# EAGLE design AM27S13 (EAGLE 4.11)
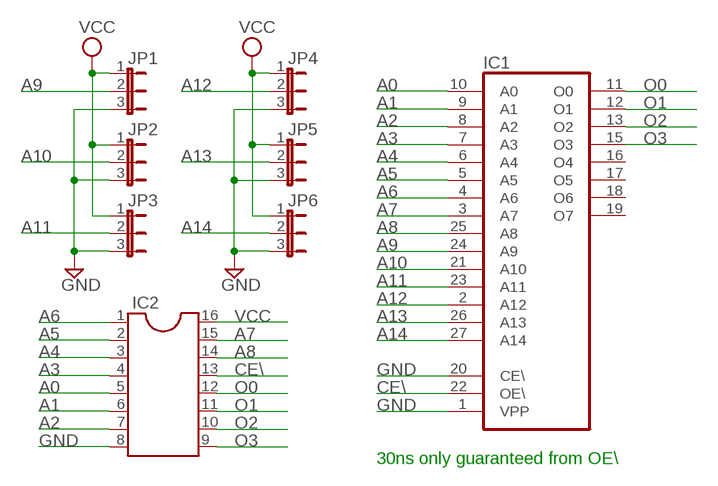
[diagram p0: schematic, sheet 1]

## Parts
IC1  27256  [DIL28]
IC2  DIL16  [DIL16]
JP1  JP2E  [JP2]
JP2  JP2E  [JP2]
JP3  JP2E  [JP2]
JP4  JP2E  [JP2]
JP5  JP2E  [JP2]
JP6  JP2E  [JP2]

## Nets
A0: IC1.10(A0) IC2.5
A1: IC1.9(A1) IC2.6
A2: IC1.8(A2) IC2.7
A3: IC1.7(A3) IC2.4
A4: IC1.6(A4) IC2.3
A5: IC1.5(A5) IC2.2
A6: IC1.4(A6) IC2.1
A7: IC1.3(A7) IC2.15
A8: IC1.25(A8) IC2.14
A9: IC1.24(A9) JP1.2
A10: IC1.21(A10) JP2.2
A11: IC1.23(A11) JP3.2
A12: IC1.2(A12) JP4.2
A13: IC1.26(A13) JP5.2
A14: IC1.27(A14) JP6.2
CE\: IC1.22(OE\) IC2.13
GND: IC1.1(VPP) IC1.20(CE\) IC2.8 JP1.3 JP2.3 JP3.3 JP4.3 JP5.3 JP6.3
O0: IC1.11(O0) IC2.12
O1: IC1.12(O1) IC2.11
O2: IC1.13(O2) IC2.10
O3: IC1.15(O3) IC2.9
VCC: IC2.16 JP1.1 JP2.1 JP3.1 JP4.1 JP5.1 JP6.1
Unconnected: IC1.16(O4) IC1.17(O5) IC1.18(O6) IC1.19(O7)

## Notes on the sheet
- 30ns only guaranteed from OE\

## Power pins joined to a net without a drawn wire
GND: IC1.14(GND)
VCC: IC1.28(VCC)

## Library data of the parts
IC1 = memory:27256: MEMORY
IC2 = ic-package:DIL16: Dual In Line
JP1-JP6 = jumper:JP2E: JUMPER

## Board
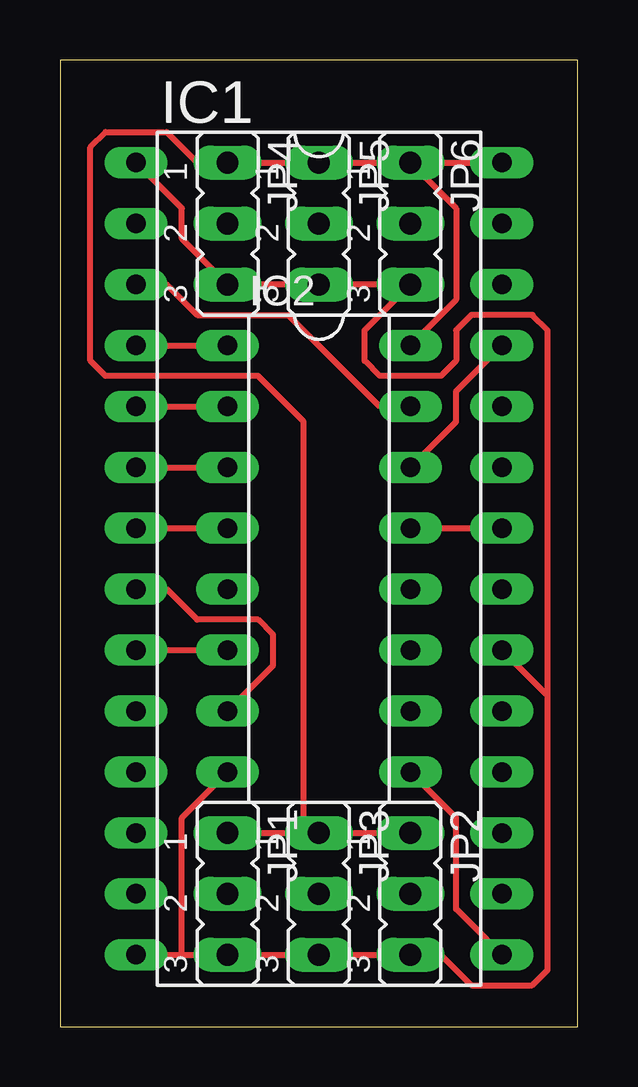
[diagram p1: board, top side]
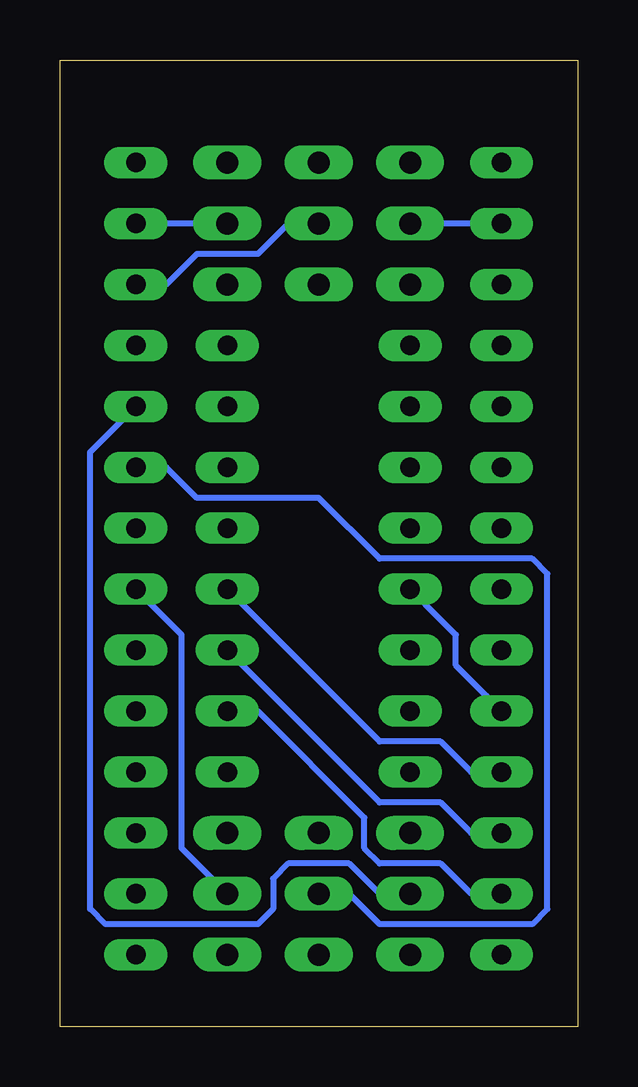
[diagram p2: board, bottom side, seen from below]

Size 21.57 x 40.31 mm. Coordinates in mm from the lower left corner, seen from the top.
Outline: 0,0 21.57,0 21.57,40.31 0,40.31 0,0
Copper layers (1*16): Top 0.035mm / dielectric 1.5mm / Bottom 0.035mm
Design rules "olimex8mil": minimum track width 10mil, minimum drill 24mil, track to track 8mil, track to pad 8mil, pad to pad 8mil, via to via 8mil, smd to smd 8mil, copper to edge 40mil, drill to drill 10mil, minimum pad ring 10mil, minimum via ring 8mil, stop-mask expansion 0mil, vias tented up to drill 0mil, thermal gap 10mil

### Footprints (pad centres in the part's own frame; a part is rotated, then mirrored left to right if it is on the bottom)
DIL28 = drill 0.813 long: 1 -16.51,-7.62; 2 -13.97,-7.62; 3 -11.43,-7.62; 4 -8.89,-7.62; 5 -6.35,-7.62; 6 -3.81,-7.62; 7 -1.27,-7.62; 8 1.27,-7.62; 9 3.81,-7.62; 10 6.35,-7.62; 11 8.89,-7.62; 12 11.43,-7.62; 13 13.97,-7.62; 14 16.51,-7.62; 15 16.51,7.62; 16 13.97,7.62; 17 11.43,7.62; 18 8.89,7.62; 19 6.35,7.62; 20 3.81,7.62; 21 1.27,7.62; 22 -1.27,7.62; 23 -3.81,7.62; 24 -6.35,7.62; 25 -8.89,7.62; 26 -11.43,7.62; 27 -13.97,7.62; 28 -16.51,7.62
DIL16 = drill 0.813 long: 1 -8.89,-3.81; 2 -6.35,-3.81; 3 -3.81,-3.81; 4 -1.27,-3.81; 5 1.27,-3.81; 6 3.81,-3.81; 7 6.35,-3.81; 8 8.89,-3.81; 9 8.89,3.81; 10 6.35,3.81; 11 3.81,3.81; 12 1.27,3.81; 13 -1.27,3.81; 14 -3.81,3.81; 15 -6.35,3.81; 16 -8.89,3.81
JP2 = drill 0.914 long: 1 -2.54,0; 2 0,0; 3 2.54,0

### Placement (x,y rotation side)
IC1  10.79,19.52 270 top
IC2  10.79,19.52 270 top
JP1  6.98,5.55 270 top
JP2  14.6,5.55 270 top
JP3  10.79,5.55 270 top
JP4  6.98,33.49 270 top
JP5  10.79,33.49 270 top
JP6  14.6,33.49 270 top

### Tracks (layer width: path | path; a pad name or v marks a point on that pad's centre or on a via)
A0
  Bottom 0.254: IC1.10 3.8,13.81 5.08,15.08 5.08,16.34 6.34,17.61 IC2.5
A1
  Top 0.254: IC1.9 4.44,15.71 5.71,15.71 IC2.6
A2
  Top 0.254: IC2.7 7.62,13.81 8.89,15.08 8.89,16.34 8.25,16.98 5.71,16.98 4.44,18.25 IC1.8
A3
  Top 0.254: IC1.7 4.44,20.79 5.71,20.79 IC2.4
A4
  Top 0.254: IC1.6 4.44,23.33 5.71,23.33 IC2.3
A5
  Top 0.254: IC1.5 4.44,25.87 5.71,25.87 IC2.2
A6
  Top 0.254: IC1.4 4.44,28.41 5.71,28.41 IC2.1
A7
  Top 0.254: IC1.3 4.44,30.95 5.71,29.68 9.52,29.68 13.33,25.87 IC2.15
A8
  Top 0.254: IC2.14 15.24,23.96 16.5,25.23 16.5,26.5 17.77,27.77 IC1.25
A9
  Bottom 0.254: IC1.24 19.04,25.23 20.31,23.96 20.31,4.92 19.68,4.28 13.33,4.28 12.7,4.92 12.7,6.18 12.06,6.82 9.52,6.82 8.25,5.55 JP1.2
A10
  Bottom 0.254: IC1.21 17.77,17.61 16.5,16.34 16.5,7.46 15.24,6.18 JP2.2
A11
  Bottom 0.254: IC1.23 17.14,23.33 15.87,22.06 10.79,22.06 8.25,19.52 1.9,19.52 1.27,18.88 1.27,4.92 1.9,4.28 8.25,4.28 9.52,5.55 JP3.2
A12
  Bottom 0.254: IC1.2 4.44,33.49 5.71,33.49 JP4.2
A13
  Bottom 0.254: IC1.26 17.14,30.95 15.87,32.22 13.33,32.22 12.06,33.49 JP5.2
A14
  Bottom 0.254: IC1.27 17.14,33.49 15.87,33.49 JP6.2
CE\
  Top 0.254: IC2.13 15.87,20.79 17.14,20.79 IC1.22
GND
  Top 0.254: IC1.1 3.8,35.39 5.08,34.12 5.08,32.85 6.34,31.58 JP4.3 8.25,30.95 9.52,30.95 JP5.3 12.06,30.95 13.33,30.95 JP6.3 13.97,30.31 12.7,29.04 12.7,27.77 13.33,27.14 15.87,27.14 16.5,27.77 16.5,29.04 17.14,29.68 19.68,29.68 20.31,29.04 20.31,13.81 | 5.08,3.01 5.71,3.01 JP1.3 8.25,3.01 9.52,3.01 JP3.3 12.06,3.01 13.33,3.01 JP2.3 15.87,3.01 17.14,1.74 19.68,1.74 20.31,2.38 20.31,13.81 | 5.08,3.01 4.44,3.01 IC1.14 | 5.08,3.01 5.08,8.73 6.34,10 IC2.8 | 20.31,13.81 19.04,15.08 IC1.20
O0
  Bottom 0.254: IC1.11 4.44,10.63 5.71,11.9 8.25,11.9 13.97,17.61 IC2.12
O1
  Bottom 0.254: IC1.12 4.44,8.09 5.71,9.36 8.25,9.36 13.97,15.08 IC2.11
O2
  Bottom 0.254: IC1.13 4.44,5.55 5.71,6.82 8.25,6.82 8.89,7.46 8.89,8.73 13.33,13.17 IC2.10
O3
  Top 0.254: IC1.15 17.77,3.64 16.5,4.92 16.5,8.73 15.24,10 IC2.9
VCC
  Top 0.254: JP1.1 8.25,8.09 9.52,8.09 JP3.1 | JP2.1 13.33,8.09 12.06,8.09 JP3.1 | IC2.16 15.24,29.04 16.5,30.31 16.5,34.12 15.24,35.39 JP6.1 | IC1.28 17.14,36.03 15.87,36.03 JP6.1 | JP6.1 13.33,36.03 12.06,36.03 JP5.1 9.52,36.03 8.25,36.03 JP4.1 5.71,36.03 4.44,37.3 1.9,37.3 1.27,36.66 1.27,27.77 1.9,27.14 8.25,27.14 10.16,25.23 10.16,8.73 JP3.1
